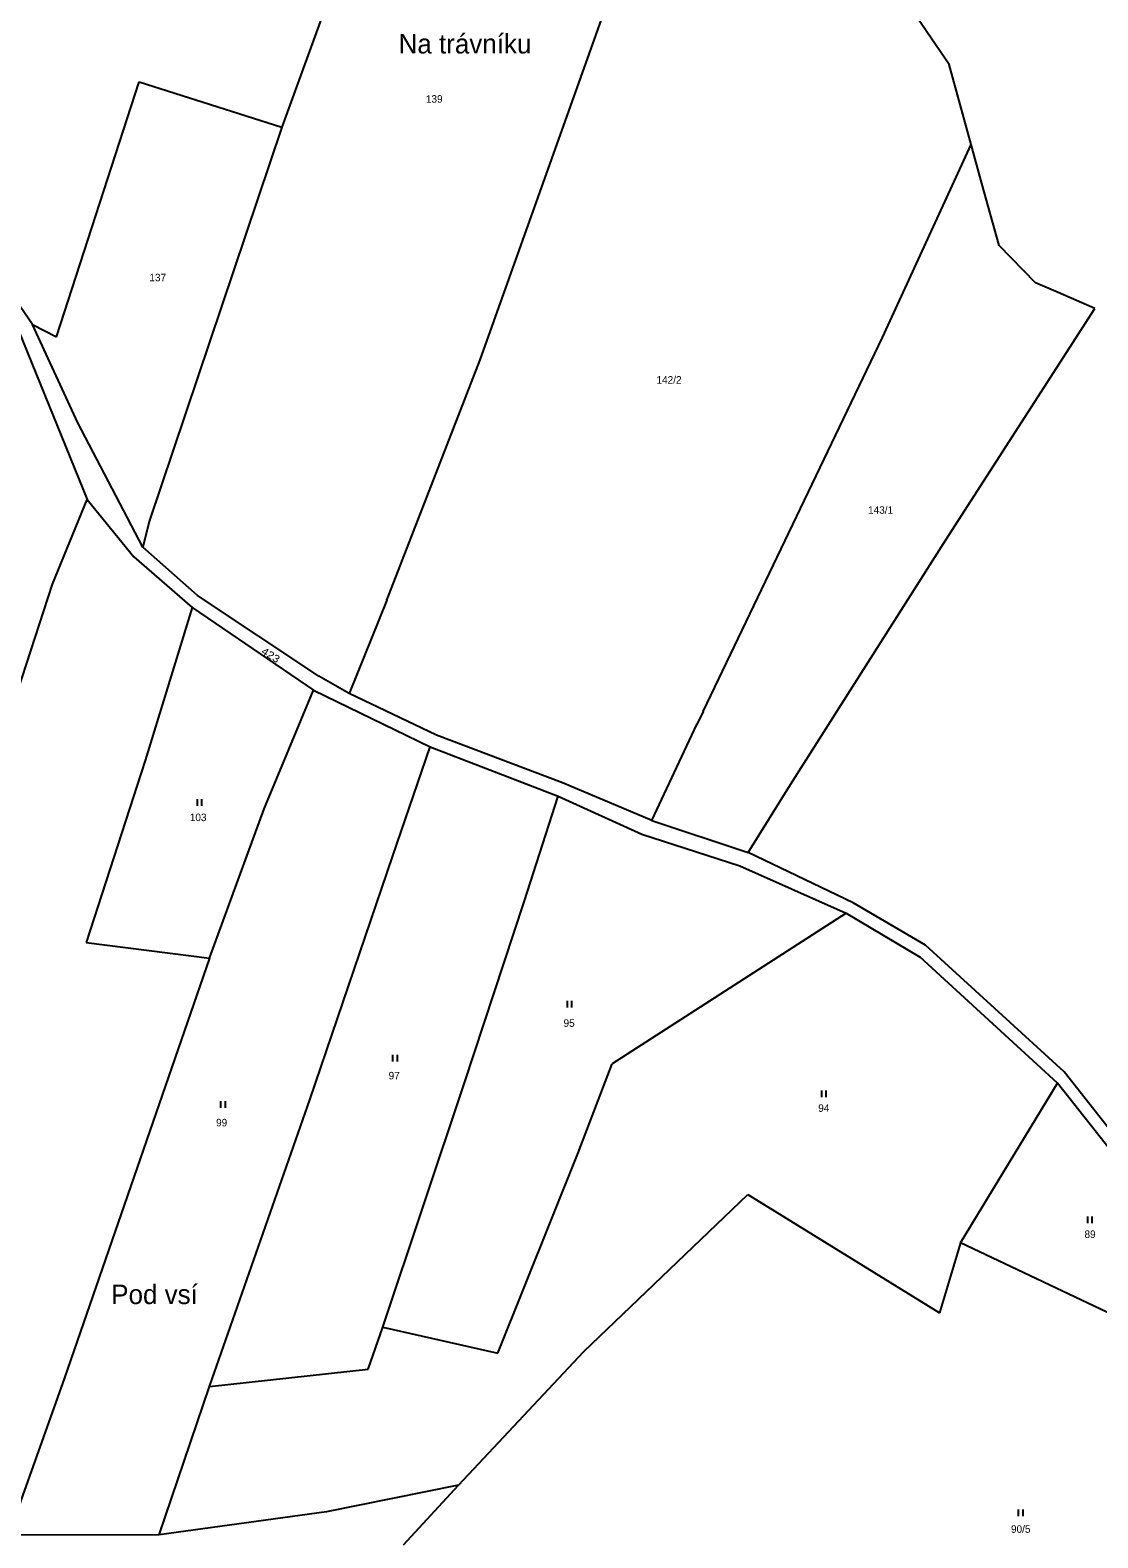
# Model space of a CAD drawing. Extents: x -791548 to -789311, y -1142631 to -1140855.
# Drawn here: x -789963.7 to -789721.8, y -1142168.7 to -1141827.2 of the extents above; entities that cross this region are included whole.
import ezdxf
from ezdxf.enums import TextEntityAlignment as Align

# ---------------------------------------------------------------- set-up
doc = ezdxf.new("R2010")
doc.units = 0
doc.header["$LTSCALE"] = 0.68
for name, color, linetype, lineweight in [('1', 7, 'Continuous', 25), ('3', 7, 'Continuous', 25), ('7', 7, 'Continuous', 13)]:
    doc.layers.add(name, color=color, linetype=linetype, lineweight=lineweight)
doc.layers.add('2', color=7, linetype='Continuous')

msp = doc.modelspace()

# ---------------------------------------------------------------- linework, layer by layer
at = {"layer": '1'}
for p, q in [((-789890.51, -1141804.68), (-789906.71, -1141849.18)), ((-789861.78, -1141901.85), (-789830.8, -1141815.01)), ((-789755.48, -1141834.95), (-789762.65, -1141824.51)), ((-789750.51, -1141853.09), (-789755.48, -1141834.95)), ((-789957.76, -1141896.63), (-789939.02, -1141838.89)), ((-789939.02, -1141838.89), (-789906.71, -1141849.18)), ((-789906.71, -1141849.18), (-789936.75, -1141938.5)), ((-789770.6, -1141896.84), (-789750.51, -1141853.09)), ((-789748.06, -1141861.96), (-789750.51, -1141853.09)), ((-789963.14, -1141893.87), (-789984.32, -1141863.23)), ((-789744.19, -1141875.96), (-789748.06, -1141861.96)), ((-789735.93, -1141884.42), (-789744.19, -1141875.96)), ((-789730.79, -1141886.64), (-789735.93, -1141884.42)), ((-789722.47, -1141890.25), (-789730.79, -1141886.64)), ((-789756.26, -1141942.63), (-789722.47, -1141890.25)), ((-789952.87, -1141916.12), (-789963.14, -1141893.87)), ((-789963.14, -1141893.87), (-789957.76, -1141896.63)), ((-789966.17, -1141895.57), (-789950.79, -1141933.49)), ((-789811.21, -1141981.49), (-789770.6, -1141896.84)), ((-789882.92, -1141956.29), (-789861.78, -1141901.85)), ((-789938.19, -1141944.29), (-789952.87, -1141916.12)), ((-789958.67, -1141952.69), (-789950.79, -1141933.49)), ((-789950.79, -1141933.49), (-789940.2, -1141946.52)), ((-789936.75, -1141938.5), (-789938.19, -1141944.29)), ((-789925.83, -1141955.23), (-789938.19, -1141944.29)), ((-789791.42, -1141998.04), (-789756.26, -1141942.63)), ((-789940.2, -1141946.52), (-789927.02, -1141958)), ((-789982.4, -1142025.56), (-789958.67, -1141952.69)), ((-789898.27, -1141973.5), (-789925.83, -1141955.23)), ((-789927.02, -1141958), (-789937.66, -1141992.59)), ((-789927.02, -1141958), (-789899.49, -1141976.71)), ((-789882.92, -1141956.29), (-789891.4, -1141977.45)), ((-789891.4, -1141977.45), (-789898.27, -1141973.5)), ((-789910.67, -1142003.56), (-789899.49, -1141976.71)), ((-789899.49, -1141976.71), (-789873.06, -1141989.53)), ((-789871.68, -1141986.87), (-789891.4, -1141977.45)), ((-789811.21, -1141981.49), (-789812.64, -1141984.43)), ((-789822.89, -1142006.18), (-789812.64, -1141984.43)), ((-789881.52, -1142014.24), (-789873.06, -1141989.53)), ((-789873.06, -1141989.53), (-789844.05, -1142000.71)), ((-789843.08, -1141997.7), (-789871.68, -1141986.87)), ((-789937.66, -1141992.59), (-789951.04, -1142033.81)), ((-789822.89, -1142006.18), (-789843.08, -1141997.7)), ((-789801.02, -1142013.46), (-789791.42, -1141998.04)), ((-789923.1, -1142037.41), (-789910.67, -1142003.56)), ((-789851.76, -1142024.6), (-789844.05, -1142000.71)), ((-789844.05, -1142000.71), (-789825.11, -1142009.32)), ((-789822.89, -1142006.18), (-789801.02, -1142013.46)), ((-789825.11, -1142009.32), (-789802.92, -1142016.44)), ((-789777.25, -1142024.86), (-789801.02, -1142013.46)), ((-789900.33, -1142069.49), (-789881.52, -1142014.24)), ((-789802.92, -1142016.44), (-789778.83, -1142027.17)), ((-789865.39, -1142065.88), (-789851.76, -1142024.6)), ((-789778.83, -1142027.17), (-789831.82, -1142061.33)), ((-789778.83, -1142027.17), (-789762.03, -1142037.17)), ((-789760.88, -1142034.44), (-789777.25, -1142024.86)), ((-789951.04, -1142033.81), (-789923.1, -1142037.41)), ((-789729.47, -1142063.14), (-789760.88, -1142034.44)), ((-789923.1, -1142037.41), (-789955.95, -1142132.43)), ((-789730.93, -1142065.73), (-789762.03, -1142037.17)), ((-789839.55, -1142081.46), (-789831.82, -1142061.33)), ((-789712.24, -1142084.98), (-789729.47, -1142063.14)), ((-789883.83, -1142120.95), (-789865.39, -1142065.88)), ((-789752.9, -1142101.84), (-789730.93, -1142065.73)), ((-789717.6, -1142082.61), (-789730.93, -1142065.73)), ((-789923.06, -1142134.41), (-789900.33, -1142069.49)), ((-789857.73, -1142126.85), (-789839.55, -1142081.46)), ((-789838.25, -1142126.46), (-789801.1, -1142090.9)), ((-789801.1, -1142090.9), (-789757.7, -1142117.73)), ((-789752.9, -1142101.84), (-789757.7, -1142117.73)), ((-789705.7, -1142124.22), (-789752.9, -1142101.84)), ((-789887.15, -1142130.45), (-789883.83, -1142120.95)), ((-789883.83, -1142120.95), (-789857.73, -1142126.85)), ((-789866.64, -1142156.74), (-789838.25, -1142126.46)), ((-789955.95, -1142132.43), (-789968.63, -1142168.11)), ((-789923.06, -1142134.41), (-789887.15, -1142130.45)), ((-789934.5, -1142168), (-789923.06, -1142134.41)), ((-789866.64, -1142156.74), (-789896.6, -1142162.79)), ((-789879.15, -1142170.27), (-789866.64, -1142156.74)), ((-789896.6, -1142162.79), (-789934.5, -1142168)), ((-789934.5, -1142168), (-789968.63, -1142168.11))]:
    msp.add_line(p, q, dxfattribs=at)
at = {"layer": '3'}
for p, q in [((-789925.791, -1142002.87), (-789925.791, -1142001.37)), ((-789924.79, -1142002.87), (-789924.79, -1142001.37)), ((-789841.981, -1142048.57), (-789841.981, -1142047.07)), ((-789840.98, -1142048.57), (-789840.98, -1142047.07)), ((-789881.511, -1142060.76), (-789881.511, -1142059.26)), ((-789880.51, -1142060.76), (-789880.51, -1142059.26)), ((-789784.331, -1142068.88), (-789784.331, -1142067.38)), ((-789783.33, -1142068.88), (-789783.33, -1142067.38)), ((-789920.471, -1142071.26), (-789920.471, -1142069.76)), ((-789919.47, -1142071.26), (-789919.47, -1142069.76)), ((-789724.101, -1142097.38), (-789724.101, -1142095.88)), ((-789723.1, -1142097.38), (-789723.1, -1142095.88)), ((-789739.751, -1142163.76), (-789739.751, -1142162.26)), ((-789738.75, -1142163.76), (-789738.75, -1142162.26))]:
    msp.add_line(p, q, dxfattribs=at)

# ---------------------------------------------------------------- texts
at = {"layer": '2'}
for s, p in [('139', (-789872.159, -1141843.622)), ('137', (-789934.809, -1141884.072)), ('142/2', (-789818.97, -1141907.262)), ('143/1', (-789771.03, -1141936.732)), ('103', (-789925.649, -1142006.342)), ('95', (-789841.599, -1142052.942)), ('97', (-789881.229, -1142064.842)), ('94', (-789783.899, -1142072.192)), ('99', (-789920.319, -1142075.482)), ('89', (-789723.569, -1142100.762)), ('90/5', (-789739.279, -1142167.542))]:
    msp.add_text(s, height=1.7, dxfattribs=at).set_placement(p, align=Align.CENTER)
at = {"layer": '2', "width": 1.15}
msp.add_text('423', height=1.7, rotation=328, dxfattribs=at).set_placement((-789909.6604, -1141969.4601), align=Align.CENTER)
at = {"layer": '7'}
for s, p in [('Na trávníku', (-789880.23, -1141832.48)), ('Pod vsí', (-789945.34, -1142115.74))]:
    msp.add_text(s, height=4.4, dxfattribs=at).set_placement(p)

doc.saveas('drawing.dxf')
